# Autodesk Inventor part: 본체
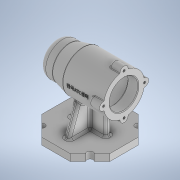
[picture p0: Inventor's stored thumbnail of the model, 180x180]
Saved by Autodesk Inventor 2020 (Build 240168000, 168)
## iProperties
Created: 2021-01
Part Number: 본체
Material: 일반
Document SubType Name: Modeling
Designer: PC2-08
Density: 1 g/cm^3
Appearance: 기본값
Author: PC2-08
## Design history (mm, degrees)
sketch "스케치2"
  geometry: L1 (50, 75)-(-50, 75); L2 (28.868, 0)-(-28.868, 0) reference; L3 (-28.868, 0)-(-57.735, 0) reference; L4 (50, 75)-(50, 100); L5 (50, 100)-(30, 100); L6 (30, 100)-(10, 105); L7 (10, 105)-(-50, 105); L8 (-50, 105)-(-50, 75); L9 (44, 75)-(44, 85.5); L10 (44, 85.5)-(41, 85.5); L11 (41, 85.5)-(41, 91); L12 (41, 91)-(37, 91); L13 (37, 91)-(37, 92.5); L14 (37, 92.5)-(19, 92.5); L15 (19, 92.5)-(19, 96); L16 (19, 96)-(7, 96); L17 (7, 96)-(7, 99); L18 (7, 99)-(-35, 99); L19 (-35, 99)-(-35, 96); L20 (-35, 96)-(-50, 96); 3 further points
  constraints: 36 end point, 10 perpendicular, 3 vertical, 2 horizontal, 2 midpoint, 2 parallel, 2 point on line, 1 vertical alignment
  dimensions: "d3" = 100 distance of L1.start L1.end; "d4" = 75 distance between parallel lines of L3 L1; "d5" = 60 diameter of L7 L1; "d6" = 50 diameter of L5 L1; "d7" = 20 distance of L4.end L5.end; "d8" = 40 distance from line of L4 L6.end; "d9" = 3 distance of L9.end L10.end; "d10" = 4 distance of L11.end L12.end; "d11" = 18 distance of L13.end L14.end; "d12" = 12 distance of L15.end L16.end; "d13" = 42 distance of L17.end L18.end; "d14" = 15 distance of L19.end L20.end; "d15" = 21 diameter of L9.end L1; "d16" = 32 diameter of L12 L1; "d17" = 35 diameter of L14 L1; "d18" = 42 diameter of L16 L1; "d19" = 48 diameter of L18 L1; "d20" = 42 diameter of L20 L1
revolve "회전1" sketch "스케치2" stored, may be unused: angle "d21" = 90 deg
sketch "스케치3" dims "d22" = 100
  geometry: L1 (20.711, 50)-(50, 20.711); L2 (50, 20.711)-(50, -20.711); L3 (50, -20.711)-(20.711, -50); L4 (20.711, -50)-(-20.711, -50); L5 (-20.711, -50)-(-50, -20.711); L6 (-50, -20.711)-(-50, 20.711); L7 (-50, 20.711)-(-20.711, 50); L8 (-20.711, 50)-(20.711, 50); 4 further points
  constraints: 16 end point, 2 coincident, 2 vertical alignment, 1 midpoint, 19 other
extrude "돌출2" join sketch "스케치3" distance "d23" = 10; taper "d24" = 0 deg
sketch "스케치4"
  geometry: L1 (-20.711, 10)-(20.711, 10) reference; L2 (-50, 10)-(-20.711, 10) reference; L3 (20.711, 10)-(50, 10) reference; L4 (19.606, 52.293)-(35, 10); L5 (-19.606, 52.293)-(-35, 10); L6 (-50, 0)-(-50, 10) reference; L7 (50, 0)-(50, 10) reference; L8 (35, 10)-(-35, 10); A1 r 30 centre (0, 75) between (19.606, 52.293) and (-19.606, 52.293) reference; A2 r 30 centre (0, 75) between (-19.606, 52.293) and (19.606, 52.293); 1 further point
  constraints: 6 end point, 4 point on circle, 2 point on line, 1 centre point, 1 collinear, 1 concentric
  dimensions: "d25" = 15 distance from line of L6 L5.end; "d26" = 15 distance from line of L7 L4.end; "d27" = 110 deg angle of L2 L5; "d28" = 110 deg angle of L3 L4
extrude "돌출3" join sketch "스케치4" stored distance "d29" = 8; taper "d30" = 0 deg
fillet "모깎기1" dims "d36" = 3
fillet "모깎기2" dims "d37" = 3
fillet "모깎기3" dims "d38" = 0.3
chamfer "모따기1" distance "d39" = 1; stored, may be unused: second distance "d40" = 2, angle "d41" = 45 deg
sketch "스케치6"
  geometry: L1 (-20.711, 50)-(-50, 20.711) reference; C1 r 4.5 at (-35.355, 35.355); 1 further point
  constraints: 1 centre point, 1 midpoint
  dimensions: "d42" = 9 diameter of C1
extrude "돌출5" cut sketch "스케치6" stored distance "d43" = 8; taper "d44" = 0 deg
sketch "스케치7"
  geometry: L1 (-50, -20.711)-(-20.711, -50) reference; L2 (50, 20.711)-(20.711, 50) reference; L3 (20.711, -50)-(50, -20.711) reference; C1 r 4.5 at (-35.355, -35.355); C2 r 4.5 at (35.355, 35.355); C3 r 4.5 at (35.355, -35.355); 1 further point
  constraints: 3 centre point, 3 midpoint
  dimensions: "d45" = 9 diameter of C1; "d46" = 9 diameter of C2; "d47" = 9 diameter of C3
extrude "돌출6" cut sketch "스케치7" distance "d48" = 20; taper "d49" = 0 deg
sketch "스케치8"
  geometry: A1 r 30 centre (0, 0) between (0, 30) and (-5.97, 29.4) reference; A2 r 6 centre (0, 30) between (5.97, 29.4) and (-5.97, 29.4); 1 further point
  constraints: 5 point on circle, 1 centre point, 1 vertical alignment
  dimensions: "d50" = 6 radius of A2
extrude "돌출7" join sketch "스케치8" distance "d51" = 16; taper "d52" = 0 deg
fillet "모깎기4" dims "d56" = 10
fillet "모깎기5" dims "d57" = 3
fillet "모깎기6" dims "d58" = 1
sketch "스케치9"
  geometry: L1 (10, 45)-(30, 50) reference; L2 (-33, 45)-(10, 45) reference; L3 (20.711, 10)-(32.173, 10) reference; L4 (-32.173, 10)-(-20.711, 10) reference; L5 (19.724, 47.431)-(27, 10); L6 (-27, 45)-(-27, 10); L7 (50, 0)-(50, 10) reference; L8 (-50, 0)-(-50, 10) reference; 1 further point
  constraints: 4 end point, 4 point on line, 1 vertical
  dimensions: "d62" = 101 deg angle of L3 L5; "d63" = 23 distance from line of L7 L5.end; "d64" = 23 distance from line of L8 L6.end
feature "리브1" dims "d65" = 1, "d66" = 8, "d67" = 0, "d68" = 0, "d69" = 1, "d70" = 1
feature "리브2" dims "d71" = 1, "d72" = 8, "d73" = 0, "d74" = 0, "d75" = 1, "d76" = 1
fillet "모깎기7" dims "d77" = 3
fillet "모깎기8" dims "d78" = 3
fillet "모깎기9" dims "d79" = 3
sketch "스케치10"
  geometry: A1 r 6 centre (30, 30) between (35.998, 30.171) and (24.002, 30.171) reference; 2 further points
  constraints: 1 coincident
hole "구멍1" sketch "스케치10" at (30, 30) diameter "d80" = 3.242; stored, may be unused: countersink angle "d84" = 90 deg, drill point angle "d86" = 118 deg; dims "d81" = 8, "d82" = 4, "d83" = 2, "d85" = 10
node "작업 평면1"
sketch "스케치11"
  geometry: L1 (50, 104.226)-(50, 81.771) reference; L2 (50, 69.002)-(50, 80.998) reference; 3 further points
  constraints: 1 horizontal alignment, 1 midpoint, 1 other
  dimensions: "d91" = 38 distance from line of L1 point (12, 75)
feature "엠보싱1" sketch "스케치11" dims "d3" = 100, "d4" = 75, "d5" = 60, "d6" = 50, "d7" = 20, "d8" = 40, "d9" = 3, "d10" = 4, "d11" = 18, "d12" = 12, "d13" = 42, "d14" = 15, "d15" = 21, "d16" = 32, "d17" = 35, "d18" = 42, "d19" = 48, "d20" = 42, "d92" = 0.5, "d93" = 0
node "솔리드1"
pattern_circular "원형 패턴1" dims angle "d54" = 360 deg
pattern_circular "원형 패턴2" dims angle "d60" = 360 deg
pattern_circular "원형 패턴3" dims angle "d88" = 360 deg
feature "A9D066F2-1C7D-4E18-AEED-F7BC21143FA4" dims "d80" = 3.242, "d81" = 8, "d82" = 4, "d83" = 2, "d84" = 90 deg, "d85" = 10, "d86" = 118 deg
other parameters: "d90" = -67.5
